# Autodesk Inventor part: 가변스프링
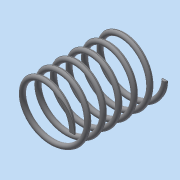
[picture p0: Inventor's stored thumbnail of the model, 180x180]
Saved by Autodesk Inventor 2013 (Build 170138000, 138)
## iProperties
Created: 2018-06
Part Number: 가변스프링
Material: 강철, 연강
Document SubType Name: Modeling
Designer: Administrator
Density: 1 g/cm^3
Mass: -0.137845 g
Surface Area: 106.475 cm^2
Volume: -0.137845 cm^3
Author: Administrator
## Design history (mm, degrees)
sketch "스케치1"
  geometry: L1 (0, 0)-(0, 73.25); L2 (0, 73.25)-(22.5, 73.25); L3 (0, 0)-(22.5, 0); C1 r 2 at (22.5, 0)
  constraints: 6 end point, 1 centre point, 1 coincident, 1 parallel, 1 perpendicular, 1 vertical
  dimensions: "d0" = 73.25 distance of L1.start L1.end (derived); "d1" = 22.5 distance of L1.end L2.end; "d2" = 22.5 distance of L1.start L3.end; "d3" = 4 diameter of C1
feature "코일1" sketch "스케치1" pitch "d4" = 10; turns "d6" = 6; dims "d5" = 73.25 (= d0), "d7" = 0, angle "d8" = 90 deg, angle "d9" = 90 deg, "d10" = 0, "d11" = 0
sketch "스케치2"
  geometry: L1 (73.25, 25)-(0, 25); L2 (0, 25)-(0, -25); L3 (0, -25)-(73.25, -25); L4 (73.25, -25)-(73.25, 25); 2 further points
  constraints: 8 end point, 2 parallel, 1 coincident, 1 horizontal, 1 midpoint, 1 perpendicular
  dimensions: "d12" = 50 distance of L3.end L1.start; "d14" = 73.25 distance of L2.end L3.end (derived)
extrude "돌출1" sketch "스케치2" stored distance "d15" = 10; taper "d16" = 0 deg
node "솔리드1"
